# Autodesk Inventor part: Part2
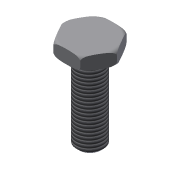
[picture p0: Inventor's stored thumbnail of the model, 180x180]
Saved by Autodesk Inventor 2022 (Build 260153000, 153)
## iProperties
Created: 2002-01
Part Number: Part2
Document SubType Name: Modeling
Designer: ***
Density: 1 g/cm^3
Material: Generic
Appearance: Default
Control State: 0
Master: False
Checked Out: False
Shininess: 77.0
Angle Display Precision: 2
Document Length Units: 11269
Document Angle Units: 11279
Document Time Units: 11290
Document Mass Units: 11283
Document Length Units Precision: 3
Document Angle Units Precision: 2
Density: 0.0
Volumn: 0.0
Area: 0.0
PropertySet Name: Model Information
Author: ***
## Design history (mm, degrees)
sketch "Sketch1"
  geometry: C1 r 20 at (0, 0)
  constraints: 1 centre point
  dimensions: "d0" = 40 diameter of C1
extrude "Extrusion1" new body sketch "Sketch1" distance "d1" = 10; taper "d2" = 0 deg
fillet "Fillet1" dims "d3" = 3
sketch "Sketch3"
  geometry: L1 (20, 0)-(10, -17.321); L2 (10, -17.321)-(-10, -17.321); L3 (-10, -17.321)-(-20, 0); L4 (-20, 0)-(-10, 17.321); L5 (-10, 17.321)-(10, 17.321); L6 (10, 17.321)-(20, 0); C1 r 17 at (0, 0) reference; 1 further point
  constraints: 12 end point, 1 coincident, 11 other
extrude "Extrusion3" sketch "Sketch3" distance "d7" = 10; taper "d8" = 0 deg
sketch "Sketch2"
  geometry: C1 r 10 at (0, 0); 1 further point
  constraints: 1 centre point, 1 coincident
  dimensions: "d4" = 20 diameter of C1
extrude "Extrusion2" join sketch "Sketch2" distance "d5" = 60; taper "d6" = 0 deg
chamfer "Chamfer1" distance "d9" = 2; stored, may be unused: second distance "d10" = 2, angle "d13" = 45 deg
thread "Thread1" dims "d11" = 10, "d12" = 0
body "Solid1"
